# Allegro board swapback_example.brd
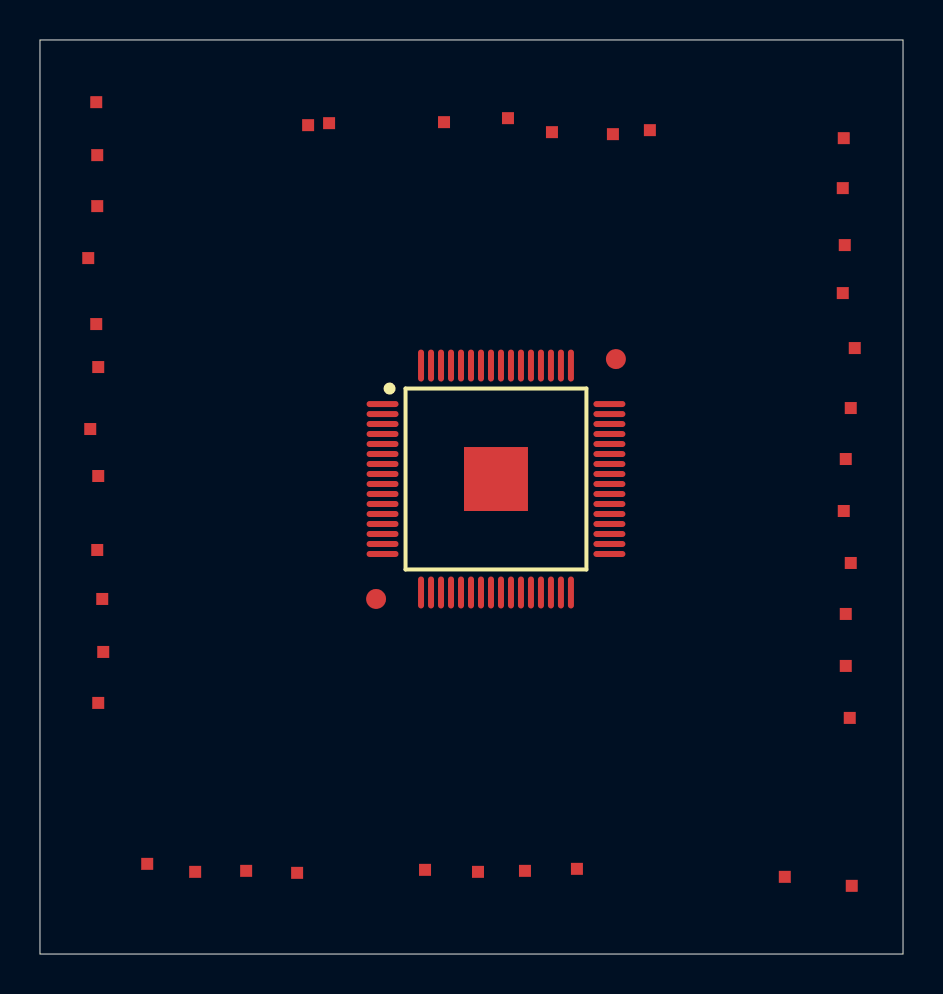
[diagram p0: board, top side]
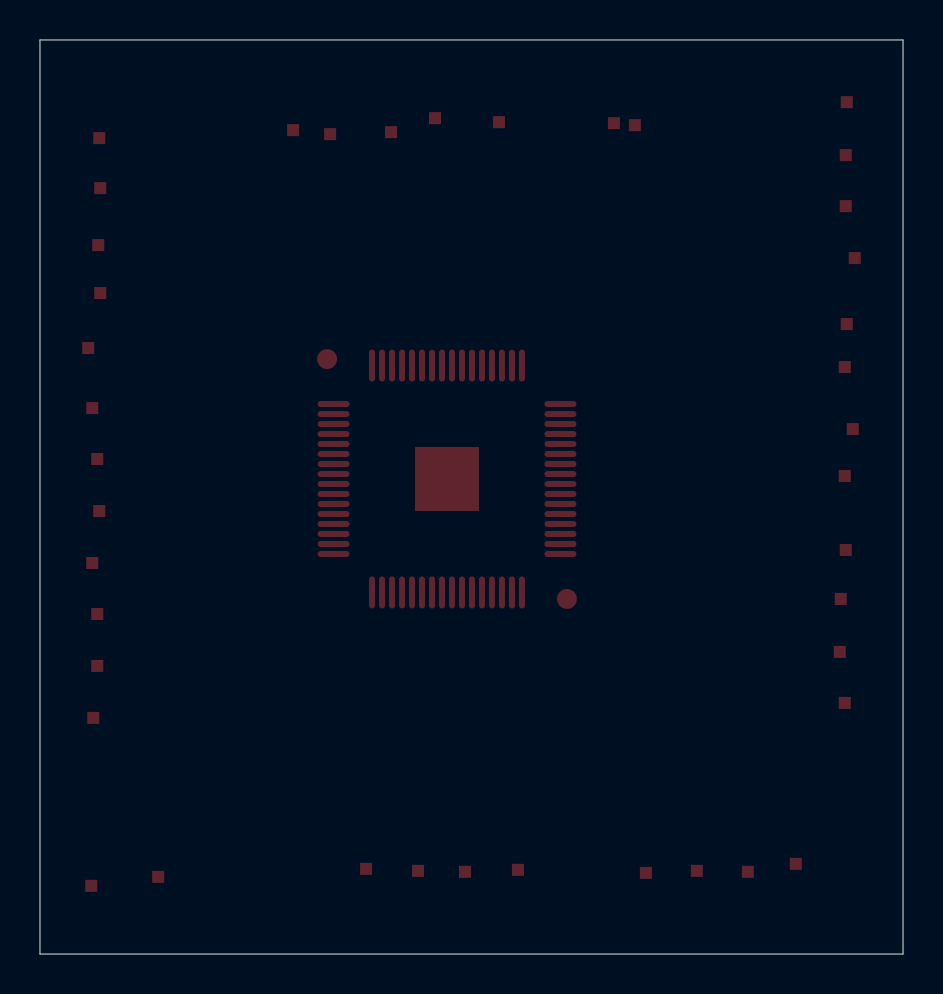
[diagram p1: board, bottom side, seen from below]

Outline 43.18 x 45.72 mm; copper layers: TOP, BOTTOM. Coordinates in mm from the lower left corner of the outline.
Outline path: 0,45.72 0,0 43.18,0 43.18,45.72 0,45.72

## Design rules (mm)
constraint set DEFAULT: min track width 0.127

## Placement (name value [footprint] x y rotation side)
TP1  TP .25mm noV  [TESTPAD_P25MM_NOVIA]  30.52 41.21 0 top
TP2  TP .25mm noV  [TESTPAD_P25MM_NOVIA]  28.66 41.01 0 top
TP3  TP .25mm noV  [TESTPAD_P25MM_NOVIA]  25.61 41.11 0 top
TP4  TP .25mm noV  [TESTPAD_P25MM_NOVIA]  23.41 41.81 0 top
TP5  TP .25mm noV  [TESTPAD_P25MM_NOVIA]  20.21 41.61 0 top
TP6  TP .25mm noV  [TESTPAD_P25MM_NOVIA]  14.46 41.56 0 top
TP7  TP .25mm noV  [TESTPAD_P25MM_NOVIA]  13.41 41.46 0 top
TP8  TP .25mm noV  [TESTPAD_P25MM_NOVIA]  2.81 42.61 0 top
TP9  TP .25mm noV  [TESTPAD_P25MM_NOVIA]  2.86 39.96 0 top
TP10  TP .25mm noV  [TESTPAD_P25MM_NOVIA]  2.86 37.41 0 top
TP11  TP .25mm noV  [TESTPAD_P25MM_NOVIA]  2.42 34.81 0 top
TP12  TP .25mm noV  [TESTPAD_P25MM_NOVIA]  2.81 31.51 0 top
TP13  TP .25mm noV  [TESTPAD_P25MM_NOVIA]  2.92 29.36 0 top
TP14  TP .25mm noV  [TESTPAD_P25MM_NOVIA]  2.51 26.26 0 top
TP15  TP .25mm noV  [TESTPAD_P25MM_NOVIA]  2.92 23.91 0 top
TP16  TP .25mm noV  [TESTPAD_P25MM_NOVIA]  2.86 20.21 0 top
TP17  TP .25mm noV  [TESTPAD_P25MM_NOVIA]  3.11 17.76 0 top
TP18  TP .25mm noV  [TESTPAD_P25MM_NOVIA]  3.17 15.11 0 top
TP19  TP .25mm noV  [TESTPAD_P25MM_NOVIA]  2.92 12.56 0 top
TP20  TP .25mm noV  [TESTPAD_P25MM_NOVIA]  5.37 4.51 0 top
TP21  TP .25mm noV  [TESTPAD_P25MM_NOVIA]  7.76 4.11 0 top
TP22  TP .25mm noV  [TESTPAD_P25MM_NOVIA]  10.31 4.16 0 top
TP23  TP .25mm noV  [TESTPAD_P25MM_NOVIA]  12.87 4.06 0 top
TP24  TP .25mm noV  [TESTPAD_P25MM_NOVIA]  19.27 4.21 0 top
TP25  TP .25mm noV  [TESTPAD_P25MM_NOVIA]  21.91 4.11 0 top
TP26  TP .25mm noV  [TESTPAD_P25MM_NOVIA]  24.27 4.16 0 top
TP27  TP .25mm noV  [TESTPAD_P25MM_NOVIA]  26.86 4.26 0 top
TP28  TP .25mm noV  [TESTPAD_P25MM_NOVIA]  37.27 3.86 0 top
TP29  TP .25mm noV  [TESTPAD_P25MM_NOVIA]  40.61 3.41 0 top
TP30  TP .25mm noV  [TESTPAD_P25MM_NOVIA]  40.52 11.81 0 top
TP31  TP .25mm noV  [TESTPAD_P25MM_NOVIA]  40.31 14.41 0 top
TP32  TP .25mm noV  [TESTPAD_P25MM_NOVIA]  40.31 17.01 0 top
TP33  TP .25mm noV  [TESTPAD_P25MM_NOVIA]  40.56 19.56 0 top
TP34  TP .25mm noV  [TESTPAD_P25MM_NOVIA]  40.22 22.16 0 top
TP35  TP .25mm noV  [TESTPAD_P25MM_NOVIA]  40.31 24.76 0 top
TP36  TP .25mm noV  [TESTPAD_P25MM_NOVIA]  40.56 27.31 0 top
TP37  TP .25mm noV  [TESTPAD_P25MM_NOVIA]  40.77 30.31 0 top
TP38  TP .25mm noV  [TESTPAD_P25MM_NOVIA]  40.17 33.06 0 top
TP39  TP .25mm noV  [TESTPAD_P25MM_NOVIA]  40.27 35.46 0 top
TP40  TP .25mm noV  [TESTPAD_P25MM_NOVIA]  40.17 38.31 0 top
TP41  TP .25mm noV  [TESTPAD_P25MM_NOVIA]  40.22 40.81 0 top
U1  TLK2201BIRCPR  [QFP50P1200X1200X120-65N_JUNK]  22.82 23.76 0 top

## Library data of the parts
TP1-TP41 = MINI_TP
U1 = TLK2201B

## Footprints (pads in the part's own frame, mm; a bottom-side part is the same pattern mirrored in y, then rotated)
QFP50P1200X1200X120-65N_JUNK
  round 1 smd: (-6,-6) (6,6)
  oval 1.6x0.3 smd: 1(-5.675,3.75) 2(-5.675,3.25) 3(-5.675,2.75) 4(-5.675,2.25) 5(-5.675,1.75) 6(-5.675,1.25) 7(-5.675,0.75) 8(-5.675,0.25) 9(-5.675,-0.25) 10(-5.675,-0.75) 11(-5.675,-1.25) 12(-5.675,-1.75) 13(-5.675,-2.25) 14(-5.675,-2.75) 15(-5.675,-3.25) 16(-5.675,-3.75) 33(5.675,-3.75) 34(5.675,-3.25) 35(5.675,-2.75) 36(5.675,-2.25) 37(5.675,-1.75) 38(5.675,-1.25) 39(5.675,-0.75) 40(5.675,-0.25) 41(5.675,0.25) 42(5.675,0.75) 43(5.675,1.25) 44(5.675,1.75) 45(5.675,2.25) 46(5.675,2.75) 47(5.675,3.25) 48(5.675,3.75)
  oval 0.3x1.6 smd: 17(-3.75,-5.675) 18(-3.25,-5.675) 19(-2.75,-5.675) 20(-2.25,-5.675) 21(-1.75,-5.675) 22(-1.25,-5.675) 23(-0.75,-5.675) 24(-0.25,-5.675) 25(0.25,-5.675) 26(0.75,-5.675) 27(1.25,-5.675) 28(1.75,-5.675) 29(2.25,-5.675) 30(2.75,-5.675) 31(3.25,-5.675) 32(3.75,-5.675) 49(3.75,5.675) 50(3.25,5.675) 51(2.75,5.675) 52(2.25,5.675) 53(1.75,5.675) 54(1.25,5.675) 55(0.75,5.675) 56(0.25,5.675) 57(-0.25,5.675) 58(-0.75,5.675) 59(-1.25,5.675) 60(-1.75,5.675) 61(-2.25,5.675) 62(-2.75,5.675) 63(-3.25,5.675) 64(-3.75,5.675)
  rect 3.2x3.2 smd: EPAD(0,0)
TESTPAD_P25MM_NOVIA
  rect 0.6x0.6 smd: 1(0,0)

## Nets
GND_SIGNAL: U1.1 U1.14 U1.21 U1.25 U1.33 U1.46 U1.51 U1.58 U1.64 U1.EPAD
VCC: U1.5 U1.10 U1.37 U1.42
ENABLE: TP26.1 U1.28
JTDI: TP41.1 U1.48
JTDO: TP25.1 U1.27
JTMS: TP4.1 U1.55
JTRSTN: TP5.1 U1.56
LOOPEN: TP21.1 U1.19
LOS: TP24.1 U1.26
MODSEL: TP18.1 U1.15
PRBSEN: TP19.1 U1.16
RCB0: TP28.1 U1.31
RCB1: TP27.1 U1.30
RCBMODE: TP29.1 U1.32
RD0: TP39.1 U1.45
RD1: TP38.1 U1.44
RD2: TP37.1 U1.43
RD3: TP36.1 U1.41
RD4: TP35.1 U1.40
RD5: TP34.1 U1.39
RD6: TP33.1 U1.38
RD7: TP32.1 U1.36
RD8: TP31.1 U1.35
RD9: TP30.1 U1.34
REFCLK: TP22.1 U1.22
RXN: TP2.1 U1.52
RXP: TP3.1 U1.54
SYNC: TP40.1 U1.47
SYNCEN: TP23.1 U1.24
TCK: TP1.1 U1.49
TD0: TP8.1 U1.2
TD1: TP9.1 U1.3
TD2: TP10.1 U1.4
TD3: TP11.1 U1.6
TD4: TP12.1 U1.7
TD5: TP13.1 U1.8
TD6: TP14.1 U1.9
TD7: TP15.1 U1.11
TD8: TP16.1 U1.12
TD9: TP17.1 U1.13
TESTEN: TP20.1 U1.17
TXN: TP6.1 U1.61
TXP: TP7.1 U1.62
N09924: U1.50 U1.53 U1.57 U1.59 U1.60 U1.63
N10926: U1.18(VDDPLL) U1.20 U1.23 U1.29
